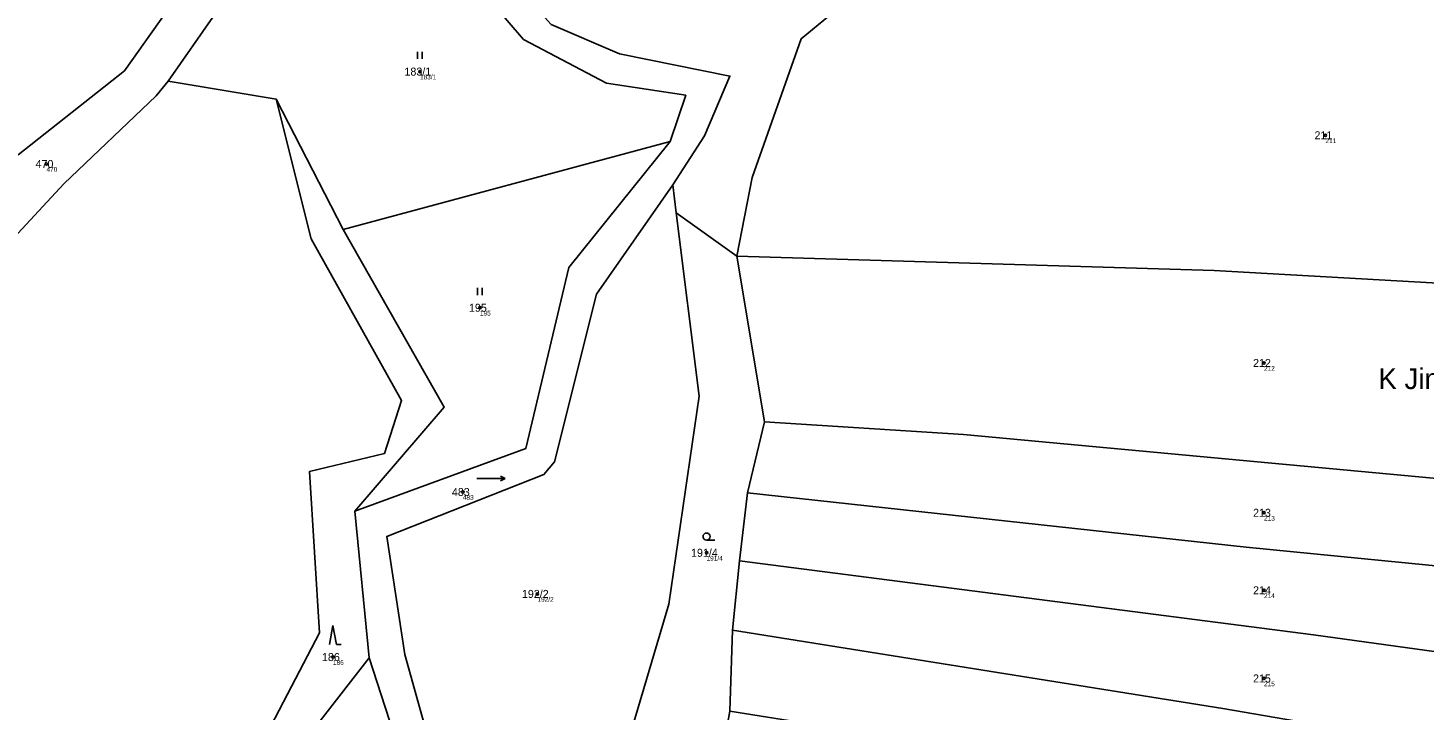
# Model space of a CAD drawing. Extents: x -700238 to -698499, y -1070626 to -1068006.
# Drawn here: x -699496.9 to -699200.2, y -1068910.8 to -1068765.8 of the extents above; entities that cross this region are included whole.
import ezdxf

# ---------------------------------------------------------------- set-up
doc = ezdxf.new("R2010")
doc.units = 0
for name, color, linetype in [('Definiční body', 7, 'Continuous'), ('Hranice parcel', 7, 'Continuous'), ('Parcelní čísla', 7, 'Continuous'), ('Polygon parcely', 7, 'Continuous'), ('Pop  PČ popisy', 7, 'Continuous'), ('Značky kultur', 7, 'Continuous')]:
    doc.layers.add(name, color=color, linetype=linetype)

msp = doc.modelspace()

# ---------------------------------------------------------------- linework, layer by layer
at = {"layer": 'Definiční body'}
for centre in [(-699413.56, -1068775.06994), (-699221.17, -1068788.60994), (-699492.91, -1068794.70994), (-699400.82, -1068825.27994), (-699234.23, -1068837.02994), (-699404.45, -1068864.45994), (-699234.23, -1068868.87994), (-699352.67, -1068877.37994), (-699234.23, -1068885.35994), (-699388.6, -1068886.12994), (-699432.05, -1068899.54994), (-699234.23, -1068904.09994)]:
    msp.add_circle(centre, 0.25, dxfattribs=at)
at = {"layer": 'Hranice parcel'}
for p, q in [((-699444.09, -1068780.91), (-699467.03, -1068777.07)), ((-699429.91, -1068808.67), (-699444.09, -1068780.91)), ((-699429.91, -1068808.67), (-699360.38, -1068789.9)), ((-699359.15, -1068805.09), (-699359.83, -1068799.14)), ((-699346.21, -1068814.3), (-699359.15, -1068805.09)), ((-699340.34, -1068849.53), (-699346.21, -1068814.3)), ((-699343.95, -1068864.6), (-699340.34, -1068849.53)), ((-699345.65, -1068879.11), (-699343.95, -1068864.6)), ((-699424.37, -1068899.73), (-699427.39, -1068868.56)), ((-699347.13, -1068893.81), (-699345.65, -1068879.11)), ((-699347.73, -1068911.07), (-699347.13, -1068893.81))]:
    msp.add_line(p, q, dxfattribs=at)
for points in [[(-699356.75, -1068711.69), (-699367.23, -1068721.51), (-699371.39, -1068734.85), (-699392.66, -1068747.2), (-699398.53, -1068760.17), (-699391.56, -1068768.24), (-699373.96, -1068777.54), (-699357.08, -1068780.11), (-699360.38, -1068789.9)], [(-699316.06, -1068730.07), (-699321.93, -1068729.44), (-699337.26, -1068722.8), (-699348.26, -1068726.55), (-699357.08, -1068720.19), (-699361.09, -1068723.38), (-699365.93, -1068739.63), (-699388.09, -1068752.22), (-699391.67, -1068758.31), (-699385.67, -1068765.06), (-699371.18, -1068771.31), (-699347.69, -1068776.03), (-699353.13, -1068788.73), (-699359.83, -1068799.14)], [(-699467.03, -1068777.07), (-699457.09, -1068762.8), (-699446.16, -1068746.43)], [(-699464.55, -1068758.22), (-699476.32, -1068774.9), (-699498.94, -1068792.74)], [(-699346.21, -1068814.3), (-699343.01, -1068797.58), (-699332.59, -1068768.07), (-699320.54, -1068758.12)], [(-699467.03, -1068777.07), (-699469.58, -1068780.23), (-699489.21, -1068798.95), (-699536.5, -1068849.9), (-699549.19, -1068864.03), (-699580.35, -1068895.36), (-699603.8, -1068919.93)], [(-699564.08, -1068981.34), (-699516.89, -1068958.22), (-699501.19, -1068954.74), (-699489.25, -1068955.25), (-699477.59, -1068953.57), (-699466.57, -1068947.54), (-699450.3, -1068923.87), (-699434.9, -1068894.43), (-699437.02, -1068860.08), (-699421.12, -1068856.29), (-699417.46, -1068845.03), (-699436.71, -1068810.63), (-699444.09, -1068780.91)], [(-699360.38, -1068789.9), (-699381.9, -1068816.69), (-699391.08, -1068855.23), (-699427.39, -1068868.56)], [(-699359.83, -1068799.14), (-699376.05, -1068822.41), (-699385.01, -1068858.02), (-699387.23, -1068860.71), (-699420.63, -1068873.89), (-699416.74, -1068899.02), (-699410.61, -1068921.12)], [(-699359.15, -1068805.09), (-699354.24, -1068844.09), (-699360.66, -1068888.29), (-699372.07, -1068926.78)], [(-699427.39, -1068868.56), (-699408.44, -1068846.42), (-699429.91, -1068808.67)], [(-699346.21, -1068814.3), (-699244.79, -1068817.34), (-699112.1, -1068824.87)], [(-699340.34, -1068849.53), (-699298.11, -1068852.24), (-699123.65, -1068868.45)], [(-699343.95, -1068864.6), (-699238.04, -1068876.16), (-699184.84, -1068881.42), (-699128.48, -1068889.06)], [(-699345.65, -1068879.11), (-699223.74, -1068894.86), (-699178.12, -1068901.11), (-699133.96, -1068909.29)], [(-699347.13, -1068893.81), (-699242.99, -1068910.5), (-699140.02, -1068928.19)], [(-699487.89, -1068960.32), (-699474.54, -1068956.68), (-699465.32, -1068952.35), (-699424.37, -1068899.73)], [(-699485.61, -1068969.54), (-699464.16, -1068973.83), (-699446.31, -1068964.48), (-699424.28, -1068940.23), (-699417.45, -1068920.9), (-699424.37, -1068899.73)]]:
    msp.add_lwpolyline(points, dxfattribs=at)
at = {"layer": 'Polygon parcely'}
for points in [[(-699536.5, -1068849.9), (-699489.21, -1068798.95), (-699469.58, -1068780.23), (-699467.03, -1068777.07), (-699457.09, -1068762.8), (-699446.16, -1068746.43), (-699415.83, -1068695.7), (-699402.82, -1068679.09), (-699399.84, -1068675.68), (-699389.04, -1068660.7), (-699391.02, -1068656.78), (-699395.63, -1068652.94), (-699417.63, -1068634.59), (-699456.64, -1068610.59), (-699466.71, -1068604.39), (-699489.31, -1068592.29), (-699514.72, -1068578.68)], [(-699514.77, -1068580.92), (-699467.93, -1068606.23), (-699418.44, -1068636.97), (-699391.79, -1068658.5), (-699420.37, -1068692.98), (-699440.37, -1068723.79), (-699464.55, -1068758.22), (-699476.32, -1068774.9), (-699498.94, -1068792.74)], [(-699398.53, -1068760.17), (-699391.56, -1068768.24), (-699373.96, -1068777.54), (-699357.08, -1068780.11), (-699360.38, -1068789.9), (-699381.9, -1068816.69), (-699391.08, -1068855.23), (-699427.39, -1068868.56), (-699424.37, -1068899.73), (-699417.45, -1068920.9)], [(-699410.61, -1068921.12), (-699416.74, -1068899.02), (-699420.63, -1068873.89), (-699387.23, -1068860.71), (-699385.01, -1068858.02), (-699376.05, -1068822.41), (-699359.83, -1068799.14), (-699353.13, -1068788.73), (-699347.69, -1068776.03), (-699371.18, -1068771.31), (-699385.67, -1068765.06)], [(-699465.32, -1068952.35), (-699424.37, -1068899.73), (-699427.39, -1068868.56), (-699408.44, -1068846.42), (-699429.91, -1068808.67), (-699444.09, -1068780.91), (-699436.71, -1068810.63), (-699417.46, -1068845.03), (-699421.12, -1068856.29), (-699437.02, -1068860.08), (-699434.9, -1068894.43), (-699450.3, -1068923.87)]]:
    msp.add_lwpolyline(points, dxfattribs=at)
for points in [[(-699682.47, -1068655.58), (-699692.25, -1068684.81), (-699695.12, -1068702.49), (-699640.97, -1068718.81), (-699602.77, -1068734.4), (-699577.98, -1068745.62), (-699550.82, -1068759.4), (-699524.87, -1068774.77), (-699498.94, -1068792.74), (-699476.32, -1068774.9), (-699464.55, -1068758.22), (-699502.54, -1068733.53), (-699525.94, -1068718.9), (-699568.74, -1068696.16), (-699607.46, -1068678.07), (-699629.84, -1068668.69), (-699681, -1068651.1)], [(-699374.88, -1068691.99), (-699390.45, -1068684.47), (-699412.7, -1068716.51), (-699424.51, -1068753.75), (-699446.16, -1068746.43), (-699457.09, -1068762.8), (-699467.03, -1068777.07), (-699444.09, -1068780.91), (-699429.91, -1068808.67), (-699360.38, -1068789.9), (-699357.08, -1068780.11), (-699373.96, -1068777.54), (-699391.56, -1068768.24), (-699398.53, -1068760.17), (-699392.66, -1068747.2), (-699371.39, -1068734.85), (-699367.23, -1068721.51), (-699356.75, -1068711.69)], [(-699357.08, -1068720.19), (-699361.09, -1068723.38), (-699365.93, -1068739.63), (-699388.09, -1068752.22), (-699391.67, -1068758.31), (-699385.67, -1068765.06), (-699371.18, -1068771.31), (-699347.69, -1068776.03), (-699353.13, -1068788.73), (-699359.83, -1068799.14), (-699359.15, -1068805.09), (-699346.21, -1068814.3), (-699343.01, -1068797.58), (-699332.59, -1068768.07), (-699320.54, -1068758.12), (-699302, -1068731.73), (-699316.06, -1068730.07), (-699321.93, -1068729.44), (-699337.26, -1068722.8), (-699348.26, -1068726.55)], [(-699346.21, -1068814.3), (-699244.79, -1068817.34), (-699112.1, -1068824.87), (-699095.55, -1068762.45), (-699164.78, -1068761.6), (-699320.54, -1068758.12), (-699332.59, -1068768.07), (-699343.01, -1068797.58)], [(-699536.5, -1068849.9), (-699549.19, -1068864.03), (-699580.35, -1068895.36), (-699603.8, -1068919.93), (-699588.42, -1068936.57), (-699577.66, -1068955.53), (-699570.69, -1068974.98), (-699564.08, -1068981.34), (-699516.89, -1068958.22), (-699501.19, -1068954.74), (-699489.25, -1068955.25), (-699477.59, -1068953.57), (-699466.57, -1068947.54), (-699450.3, -1068923.87), (-699434.9, -1068894.43), (-699437.02, -1068860.08), (-699421.12, -1068856.29), (-699417.46, -1068845.03), (-699436.71, -1068810.63), (-699444.09, -1068780.91), (-699467.03, -1068777.07), (-699469.58, -1068780.23), (-699489.21, -1068798.95)], [(-699427.39, -1068868.56), (-699391.08, -1068855.23), (-699381.9, -1068816.69), (-699360.38, -1068789.9), (-699429.91, -1068808.67), (-699408.44, -1068846.42)], [(-699385.01, -1068858.02), (-699387.23, -1068860.71), (-699420.63, -1068873.89), (-699416.74, -1068899.02), (-699410.61, -1068921.12), (-699372.07, -1068926.78), (-699360.66, -1068888.29), (-699354.24, -1068844.09), (-699359.15, -1068805.09), (-699359.83, -1068799.14), (-699376.05, -1068822.41)], [(-699340.34, -1068849.53), (-699346.21, -1068814.3), (-699359.15, -1068805.09), (-699354.24, -1068844.09), (-699360.66, -1068888.29), (-699372.07, -1068926.78), (-699351.16, -1068930.36), (-699347.73, -1068911.07), (-699347.13, -1068893.81), (-699345.65, -1068879.11), (-699343.95, -1068864.6)], [(-699340.34, -1068849.53), (-699298.11, -1068852.24), (-699123.65, -1068868.45), (-699112.1, -1068824.87), (-699244.79, -1068817.34), (-699346.21, -1068814.3)], [(-699238.04, -1068876.16), (-699184.84, -1068881.42), (-699128.48, -1068889.06), (-699123.65, -1068868.45), (-699298.11, -1068852.24), (-699340.34, -1068849.53), (-699343.95, -1068864.6)], [(-699223.74, -1068894.86), (-699178.12, -1068901.11), (-699133.96, -1068909.29), (-699128.48, -1068889.06), (-699184.84, -1068881.42), (-699238.04, -1068876.16), (-699343.95, -1068864.6), (-699345.65, -1068879.11)], [(-699133.96, -1068909.29), (-699178.12, -1068901.11), (-699223.74, -1068894.86), (-699345.65, -1068879.11), (-699347.13, -1068893.81), (-699242.99, -1068910.5), (-699140.02, -1068928.19)], [(-699222.42, -1068932.84), (-699146.33, -1068948.42), (-699140.02, -1068928.19), (-699242.99, -1068910.5), (-699347.13, -1068893.81), (-699347.73, -1068911.07), (-699287.21, -1068920.71)], [(-699464.16, -1068973.83), (-699446.31, -1068964.48), (-699424.28, -1068940.23), (-699417.45, -1068920.9), (-699424.37, -1068899.73), (-699465.32, -1068952.35), (-699474.54, -1068956.68), (-699487.89, -1068960.32), (-699485.61, -1068969.54)]]:
    msp.add_lwpolyline(points, close=True, dxfattribs=at)
at = {"layer": 'Značky kultur'}
for p, q in [((-699414.071, -1068772.37), (-699414.071, -1068770.87)), ((-699413.07, -1068772.37), (-699413.07, -1068770.87)), ((-699401.331, -1068822.58), (-699401.331, -1068821.08)), ((-699400.33, -1068822.58), (-699400.33, -1068821.08)), ((-699401.473, -1068861.599), (-699395.473, -1068861.599)), ((-699395.473, -1068861.599), (-699396.45, -1068861.097)), ((-699395.473, -1068861.599), (-699396.45, -1068862.1)), ((-699352.663, -1068874.68), (-699350.913, -1068874.68)), ((-699432.05, -1068892.85), (-699432.8, -1068896.85)), ((-699431.3, -1068896.85), (-699432.05, -1068892.85)), ((-699431.3, -1068896.85), (-699430.304, -1068896.85))]:
    msp.add_line(p, q, dxfattribs=at)
msp.add_circle((-699352.66286, -1068873.92981), 0.75, dxfattribs=at)

# ---------------------------------------------------------------- texts
at = {"layer": 'Definiční body'}
for s, p in [('183/1', (-699413.56, -1068776.726)), ('211', (-699221.17, -1068790.266)), ('470', (-699492.91, -1068796.366)), ('195', (-699400.82, -1068826.936)), ('212', (-699234.23, -1068838.686)), ('483', (-699404.45, -1068866.116)), ('213', (-699234.23, -1068870.536)), ('191/4', (-699352.67, -1068879.036)), ('192/2', (-699388.6, -1068887.786)), ('214', (-699234.23, -1068887.016)), ('186', (-699432.05, -1068901.206)), ('215', (-699234.23, -1068905.756))]:
    msp.add_text(s, height=0.999996, dxfattribs=at).set_placement(p)
at = {"layer": 'Parcelní čísla'}
for s, p in [('183/1', (-699416.858, -1068775.92)), ('211', (-699223.495, -1068789.46)), ('470', (-699495.235, -1068795.56)), ('195', (-699403.145, -1068826.13)), ('212', (-699236.555, -1068837.88)), ('483', (-699406.775, -1068865.31)), ('213', (-699236.555, -1068869.729)), ('191/4', (-699355.968, -1068878.229)), ('192/2', (-699391.898, -1068886.979)), ('214', (-699236.555, -1068886.21)), ('186', (-699434.375, -1068900.4)), ('215', (-699236.555, -1068904.95))]:
    msp.add_text(s, height=1.699998, dxfattribs=at).set_placement(p)
at = {"layer": 'Pop  PČ popisy'}
msp.add_text('K Jindicím', height=4.399998, dxfattribs=at).set_placement((-699209.93, -1068842.579))

doc.saveas('drawing.dxf')
